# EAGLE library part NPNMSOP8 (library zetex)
NPN TRANSISTOR
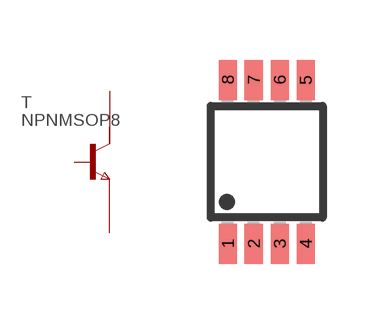
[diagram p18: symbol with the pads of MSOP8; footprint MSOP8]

Designator prefix T

## NPNMSOP8 (OC_FARNELL: unknown; OC_NEWARK: unknown)  [MSOP8]
1  E  pas
2  E1  pas
3  E2  pas
4  B  pas
5  C1  pas
6  C2  pas
7  C3  pas
8  C4  pas

## Footprint MSOP8 (pad centres in mm)
Micro Small Outline Package
smd 0.45 x 1: 1 -0.975,-2.05; 2 -0.325,-2.05; 3 0.325,-2.05; 4 0.975,-2.05; 5 0.975,2.05; 6 0.325,2.05; 7 -0.325,2.05; 8 -0.975,2.05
